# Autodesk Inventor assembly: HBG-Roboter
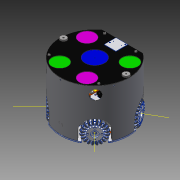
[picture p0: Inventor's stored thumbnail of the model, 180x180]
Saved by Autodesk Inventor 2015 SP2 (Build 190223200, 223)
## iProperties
Created: 2012-07
Part Number: HBG-Roboter
Document SubType Name: Assembly
Designer: rYan
Mass: 3595.73 g
Surface Area: 9246.26 cm^2
Volume: 1408.82 cm^3
Density: 2.5523 g/cm^3
Author: rYan
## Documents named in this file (16)
- D:\TIGERs GIT\Hardware\mechanik\2016\Inventor\HBG-Roboter.iam
- D:\TIGERs GIT\Hardware\mechanik\2016\Inventor\Antrieb\OBG-AntriebA.iam
- D:\TIGERs GIT\Hardware\mechanik\2016\Inventor\Antrieb\OBG-AntriebB.iam
- D:\TIGERs GIT\Hardware\mechanik\2016\Inventor\Inhaltscenter\de-DE\DIN 7984\DIN 7984 - M3 x 6.ipt
- D:\TIGERs GIT\Hardware\mechanik\2016\Inventor\Testmasse.ipt
- D:\TIGERs GIT\Hardware\mechanik\2016\Inventor\Elektronik\OBG-Elektronik.iam
- D:\TIGERs GIT\Hardware\mechanik\2016\Inventor\Grundplatte.ipt
- D:\TIGERs GIT\Hardware\mechanik\2016\Inventor\Gehäuse\OBG-Gehäuse.iam
- D:\TIGERs GIT\Hardware\mechanik\2016\Inventor\Inhaltscenter\de-DE\DIN 7984\DIN 7984 - M4 x 6.ipt
- D:\TIGERs GIT\Hardware\mechanik\2016\Inventor\Inhaltscenter\en-US\DIN 7984\DIN 7984 - M4 x 6.ipt
- D:\TIGERs GIT\Hardware\mechanik\2016\Inventor\Dribbling Device\HBG-Dribbler.iam
- D:\TIGERs GIT\Hardware\mechanik\2016\Inventor\Kicker\OBG-Kicker.iam
- D:\TIGERs GIT\Hardware\mechanik\2016\Inventor\Kaufteile\Abstandsbolzen Typ A M4-65mm-SW8.ipt
- E:\Tigers SVN\mechanik\2016\Inventor\Kaufteile\Abstandsbolzen Typ A.ipt
- D:\TIGERs GIT\Hardware\mechanik\2016\Inventor\Elektronik\MG-Mouseboard.iam
- D:\TIGERs GIT\Hardware\mechanik\2016\Inventor\Kaufteile\Gelpad 10x4.ipt
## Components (46 placed, 13 different names)
1. Grundplatte:1 — Passend:1, Passend:5, Passend:6, Passend:34, Passend:35, Passend:36, Passend:37, Passend:38, Passend:39, Passend:40, Passend:41, Passend:42, Fluchtend:32, Passend:140, Passend:142, Passend:203, Einfügen:41, Einfügen:42, Passend:299, Passend:304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
2. Testmaße:1 — Fluchtend:32, Fluchtend:116
3. Gelpad 10x4:1 — Passend:323, Fluchtend:117, Fluchtend:118
4. Gelpad 10x4:2 — Fluchtend:119, Fluchtend:120, Passend:324
5. OBG-AntriebA:1 [sub-assembly] — Passend:1, Passend:34, Passend:35, Passend:283, Passend:304
6. OBG-AntriebB:2 [sub-assembly] — Passend:6, Passend:41, Passend:42, Passend:282
7. OBG-AntriebA:2 [sub-assembly] — Passend:36, Passend:37, Passend:38, Passend:281
8. OBG-AntriebB:1 [sub-assembly] — Passend:5, Passend:39, Passend:40, Passend:280
9. DIN 7984 M3 x 6:3 — Einfügen:59
10. DIN 7984 M3 x 6:4 — Einfügen:60
11. DIN 7984 M3 x 6:5 — Einfügen:61
12. DIN 7984 M3 x 6:6 — Einfügen:62
13. DIN 7984 M3 x 6:7 — Einfügen:63
14. DIN 7984 M3 x 6:8 — Einfügen:64
15. DIN 7984 M3 x 6:9 — Einfügen:65
16. DIN 7984 M3 x 6:10 — Einfügen:66
17. DIN 7984 M3 x 6:11 — Einfügen:67
18. DIN 7984 M3 x 6:12 — Einfügen:68
19. DIN 7984 M3 x 6:13 — Einfügen:69
20. DIN 7984 M3 x 6:14 — Einfügen:70
21. OBG-Kicker:1 [sub-assembly] — Passend:305, Passend:309, Passend:310
22. DIN 7984 M4 x 6:1 — Einfügen:48
23. DIN 7984 M4 x 6:2 — Einfügen:47
24. DIN 7984 M4 x 6:3 — Einfügen:43
25. DIN 7984 M4 x 6:4 — Einfügen:44
26. HBG-Dribbler:1 [sub-assembly] — Passend:299, Passend:312, Passend:313
27. DIN 7984 M4 x 6:21 — Einfügen:54
28. DIN 7984 M4 x 6:22 — Einfügen:52
29. DIN 7984 M4 x 6:23 — Einfügen:51
30. DIN 7984 M4 x 6:24 — Einfügen:53
31. MG-Mouseboard:1 [sub-assembly] — Passend:318, Passend:319, Einfügen:75, Einfügen:76, Passend:325
32. MG-Mouseboard:2 [sub-assembly] — Passend:321, Passend:322, Einfügen:77, Einfügen:78, Passend:326
33. DIN 7984 M4 x 6:25 — Einfügen:73
34. DIN 7984 M4 x 6:26 — Einfügen:74
35. OBG-Elektronik:1 [sub-assembly] — Passend:314, Passend:315, Passend:316, Einfügen:79, Einfügen:80
36. DIN 7984 M4 x 6:17 — Einfügen:41
37. DIN 7984 M4 x 6:18 — Einfügen:42
38. DIN 7984 M4 x 6:19 — Passend:140, Einfügen:56
39. DIN 7984 M4 x 6:20 — Passend:142, Einfügen:55
40. DIN 7984 M3 x 6:15 — Einfügen:75
41. DIN 7984 M3 x 6:16 — Einfügen:76
42. DIN 7984 M3 x 6:17 — Einfügen:78
43. DIN 7984 M3 x 6:18 — Einfügen:77
44. Abstandsbolzen Typ A M4-65mm-SW8:1 — Einfügen:71
45. Abstandsbolzen Typ A M4-65mm-SW8:2 — Einfügen:72
46. OBG-Gehäuse:1 [sub-assembly] — Einfügen:79, Einfügen:80
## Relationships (77: Mate 37, Insert 34, Flush 6)
- Passend:1 [Mate]: Grundplatte:1 ↔ OBG-AntriebA:1
- Passend:5 [Mate]: Grundplatte:1 ↔ OBG-AntriebB:1
- Passend:6 [Mate]: Grundplatte:1 ↔ OBG-AntriebB:2
- Passend:34 [Mate]: Grundplatte:1 ↔ OBG-AntriebA:1
- Passend:35 [Mate]: Grundplatte:1 ↔ OBG-AntriebA:1
- Passend:36 [Mate]: Grundplatte:1 ↔ OBG-AntriebA:2
- Passend:37 [Mate]: Grundplatte:1 ↔ OBG-AntriebA:2
- Passend:38 [Mate]: Grundplatte:1 ↔ OBG-AntriebA:2
- Passend:39 [Mate]: Grundplatte:1 ↔ OBG-AntriebB:1
- Passend:40 [Mate]: Grundplatte:1 ↔ OBG-AntriebB:1
- Passend:41 [Mate]: Grundplatte:1 ↔ OBG-AntriebB:2
- Passend:42 [Mate]: Grundplatte:1 ↔ OBG-AntriebB:2
- Fluchtend:32 [Flush]: Grundplatte:1 ↔ Testmaße:1
- Fluchtend:116 [Flush]: Testmaße:1
- Passend:140 [Mate]: Grundplatte:1 ↔ DIN 7984 M4 x 6:19
- Passend:142 [Mate]: Grundplatte:1 ↔ DIN 7984 M4 x 6:20
- Passend:203 [Mate]: Grundplatte:1
- Einfügen:41 [Insert]: Grundplatte:1 ↔ DIN 7984 M4 x 6:17
- Einfügen:42 [Insert]: Grundplatte:1 ↔ DIN 7984 M4 x 6:18
- Passend:280 [Mate]: OBG-AntriebB:1
- Passend:281 [Mate]: OBG-AntriebA:2
- Passend:282 [Mate]: OBG-AntriebB:2
- Passend:283 [Mate]: OBG-AntriebA:1
- Passend:299 [Mate]: Grundplatte:1 ↔ HBG-Dribbler:1
- Passend:304 [Mate]: Grundplatte:1 ↔ OBG-AntriebA:1
- Passend:305 [Mate]: Grundplatte:1 ↔ OBG-Kicker:1
- Passend:309 [Mate]: Grundplatte:1 ↔ OBG-Kicker:1
- Passend:310 [Mate]: Grundplatte:1 ↔ OBG-Kicker:1
- Einfügen:43 [Insert]: Grundplatte:1 ↔ DIN 7984 M4 x 6:3
- Einfügen:44 [Insert]: Grundplatte:1 ↔ DIN 7984 M4 x 6:4
- Einfügen:47 [Insert]: Grundplatte:1 ↔ DIN 7984 M4 x 6:2
- Einfügen:48 [Insert]: Grundplatte:1 ↔ DIN 7984 M4 x 6:1
- Einfügen:51 [Insert]: Grundplatte:1 ↔ DIN 7984 M4 x 6:23
- Einfügen:52 [Insert]: Grundplatte:1 ↔ DIN 7984 M4 x 6:22
- Einfügen:53 [Insert]: Grundplatte:1 ↔ DIN 7984 M4 x 6:24
- Einfügen:54 [Insert]: Grundplatte:1 ↔ DIN 7984 M4 x 6:21
- Passend:312 [Mate]: Grundplatte:1 ↔ HBG-Dribbler:1
- Passend:313 [Mate]: Grundplatte:1 ↔ HBG-Dribbler:1
- Passend:314 [Mate]: Grundplatte:1 ↔ OBG-Elektronik:1
- Passend:315 [Mate]: Grundplatte:1 ↔ OBG-Elektronik:1
- Passend:316 [Mate]: Grundplatte:1 ↔ OBG-Elektronik:1
- Einfügen:55 [Insert]: Grundplatte:1 ↔ DIN 7984 M4 x 6:20
- Einfügen:56 [Insert]: Grundplatte:1 ↔ DIN 7984 M4 x 6:19
- Einfügen:59 [Insert]: Grundplatte:1 ↔ DIN 7984 M3 x 6:3
- Einfügen:60 [Insert]: Grundplatte:1 ↔ DIN 7984 M3 x 6:4
- Einfügen:61 [Insert]: Grundplatte:1 ↔ DIN 7984 M3 x 6:5
- Einfügen:62 [Insert]: Grundplatte:1 ↔ DIN 7984 M3 x 6:6
- Einfügen:63 [Insert]: Grundplatte:1 ↔ DIN 7984 M3 x 6:7
- Einfügen:64 [Insert]: Grundplatte:1 ↔ DIN 7984 M3 x 6:8
- Einfügen:65 [Insert]: Grundplatte:1 ↔ DIN 7984 M3 x 6:9
- Einfügen:66 [Insert]: Grundplatte:1 ↔ DIN 7984 M3 x 6:10
- Einfügen:67 [Insert]: Grundplatte:1 ↔ DIN 7984 M3 x 6:11
- Einfügen:68 [Insert]: Grundplatte:1 ↔ DIN 7984 M3 x 6:12
- Einfügen:69 [Insert]: Grundplatte:1 ↔ DIN 7984 M3 x 6:13
- Einfügen:70 [Insert]: Grundplatte:1 ↔ DIN 7984 M3 x 6:14
- Einfügen:71 [Insert]: Grundplatte:1 ↔ Abstandsbolzen Typ A M4-65mm-SW8:1
- Einfügen:72 [Insert]: Grundplatte:1 ↔ Abstandsbolzen Typ A M4-65mm-SW8:2
- Einfügen:73 [Insert]: Grundplatte:1 ↔ DIN 7984 M4 x 6:25
- Einfügen:74 [Insert]: Grundplatte:1 ↔ DIN 7984 M4 x 6:26
- Passend:318 [Mate]: Grundplatte:1 ↔ MG-Mouseboard:1
- Passend:319 [Mate]: Grundplatte:1 ↔ MG-Mouseboard:1
- Passend:321 [Mate]: Grundplatte:1 ↔ MG-Mouseboard:2
- Passend:322 [Mate]: Grundplatte:1 ↔ MG-Mouseboard:2
- Einfügen:75 [Insert]: MG-Mouseboard:1 ↔ DIN 7984 M3 x 6:15
- Einfügen:76 [Insert]: MG-Mouseboard:1 ↔ DIN 7984 M3 x 6:16
- Einfügen:77 [Insert]: MG-Mouseboard:2 ↔ DIN 7984 M3 x 6:18
- Einfügen:78 [Insert]: MG-Mouseboard:2 ↔ DIN 7984 M3 x 6:17
- Passend:323 [Mate]: Grundplatte:1 ↔ Gelpad 10x4:1
- Fluchtend:117 [Flush]: Grundplatte:1 ↔ Gelpad 10x4:1
- Fluchtend:118 [Flush]: Grundplatte:1 ↔ Gelpad 10x4:1
- Fluchtend:119 [Flush]: Grundplatte:1 ↔ Gelpad 10x4:2
- Fluchtend:120 [Flush]: Grundplatte:1 ↔ Gelpad 10x4:2
- Passend:324 [Mate]: Grundplatte:1 ↔ Gelpad 10x4:2
- Passend:325 [Mate]: Grundplatte:1 ↔ MG-Mouseboard:1
- Passend:326 [Mate]: Grundplatte:1 ↔ MG-Mouseboard:2
- Einfügen:79 [Insert]: OBG-Elektronik:1 ↔ OBG-Gehäuse:1
- Einfügen:80 [Insert]: OBG-Elektronik:1 ↔ OBG-Gehäuse:1
